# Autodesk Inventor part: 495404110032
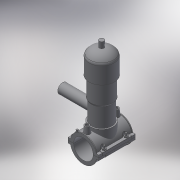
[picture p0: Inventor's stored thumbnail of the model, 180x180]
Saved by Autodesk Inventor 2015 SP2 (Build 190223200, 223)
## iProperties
Created: 2017-07
Part Number: 495404110032
Material: Generic
Description: PLASSON TAPPING VALVE 110-32
Document SubType Name: Modeling
Designer: KIM
Density: 1 g/cm^3
Appearance: Default
Author: KIM
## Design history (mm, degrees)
derived "495404-4954S4.ipt"
feature "Solid1::495404-4954S4.ipt"
feature "Solid2::495404-4954S4.ipt"
tag "TaggingFeature1"
body "Solid1"
body "Solid2"
other parameters: "d2" = 148, "d3" = 27.5, "d4" = 118, "d5" = 0, "d6" = 0.1, "d8" = 0, "d19" = 6, "d20" = 6, "d21" = 70.8, "d23" = 0, "d24" = 35.4, "d26" = 0, "d27" = 3, "d28" = 3, "d29" = 3, "d30" = 36.66667, "d31" = 6, "d32" = 0, "d33" = 0, "d34" = 0.6, "d40" = 71.5, "d47" = 114.75, "d70" = 15, "d72" = 0, "d73" = 6, "d75" = 5, "d76" = 0, "d77" = 5.5, "d78" = 85, "d79" = 15, "d80" = 47.2, "d82" = 5 deg, "d84" = 4, "d85" = 14, "d86" = 0, "d87" = 3, "d88" = 0, "d89" = 1, "d90" = 1, "d91" = 94.4, "d92" = 0, "d93" = 0.5, "d94" = 57.89474, "d96" = 141.625, "d97" = 2.36, "d98" = 0, "d120" = 140 deg, "d121" = 24.228, "d122" = 20 deg, "d123" = 275, "d124" = 82.5, "d126" = 0, "d143" = 113.3, "d145" = 21.15385, "d149" = 1.65, "d150" = 23.26923, "d153" = 118, "d154" = 0, "d156" = 68.75, "d157" = 160 deg, "d159" = 5.5, "d161" = 1.65, "d162" = 70.8, "d163" = 0, "d164" = 55, "d167" = 11, "d168" = 67.07317, "d170" = 3, "d172" = 0, "d173" = 1, "d175" = 55, "d176" = 20 deg, "d177" = 7.7, "d178" = 27.5, "d180" = 0, "d183" = 11, "d184" = 6.16, "d185" = 38.35, "d186" = 38.35, "d187" = 68.75, "d188" = 8.25, "d189" = 7.7, "d190" = 0, "d191" = 103.125, "d193" = 6.8, "d194" = 2.95, "d195" = 90 deg, "d197" = 0, "d199" = 0, "d205" = 14.64, "d206" = 81.33333, "d207" = 244, "d208" = 224.48, "d209" = 207.4, "d210" = 200.08, "d211" = 146.4, "d212" = 85.4, "d213" = 65.88, "d214" = 73.2, "d216" = 19.52, "d217" = 70.76, "d218" = 80.52, "d222" = 0, "d223" = 137.5, "d224" = 126, "d225" = 46, "d226" = 32, "d229" = 126, "d230" = 0, "B_" = 148, "H_" = 126, "L_" = 118, "d_t" = 6, "d_1" = 32, "H_1" = 46, "H_2" = 244, "d148" = 1.65, "d160" = 1.65, "d169" = 3, "d192" = 6.8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
